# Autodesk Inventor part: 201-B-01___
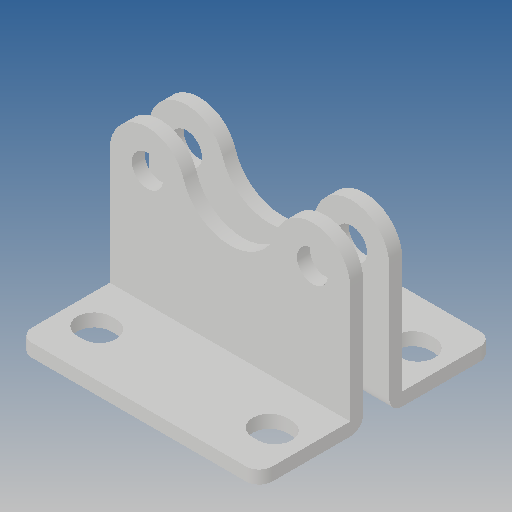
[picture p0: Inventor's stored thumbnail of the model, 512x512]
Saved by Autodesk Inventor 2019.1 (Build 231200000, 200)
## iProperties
Created: 2010-06
Part Number: 201-B-01___
Material: Ogólny
Document SubType Name: Modeling
Designer: CADENGINEERING4
Density: 1 g/cm^3
Appearance: Domyślna
Author: CADENGINEERING4
Revision Number: ANY
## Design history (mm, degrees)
feature "NONE"
feature "NONE:1"
node "Bryła1"
node "Bryła2"
